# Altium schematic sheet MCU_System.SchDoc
size A4; SheetNumber: 2; SheetTotal: 4
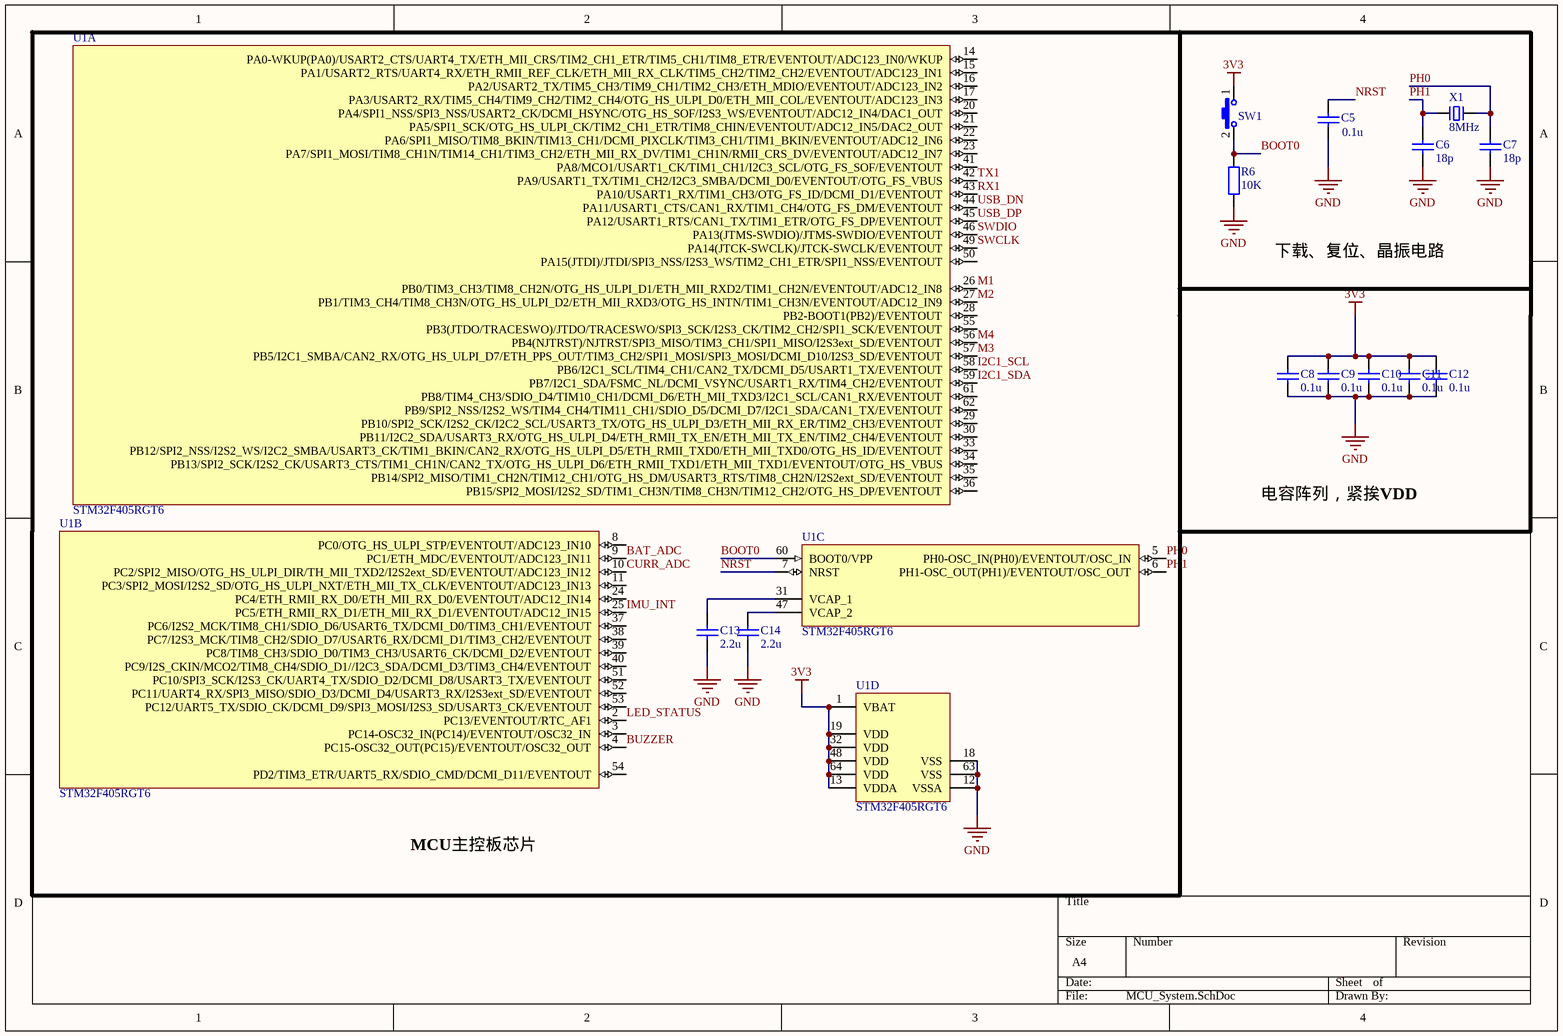
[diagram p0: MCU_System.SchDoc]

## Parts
C5  0.1u  [C0402_M]
C6  18p  [C0402_M]
C7  18p  [C0402_M]
C8  0.1u  [C0402_M]
C9  0.1u  [C0402_M]
C10  0.1u  [C0402_M]
C11  0.1u  [C0402_M]
C12  0.1u  [C0402_M]
C13  2.2u  [C0402_M]
C14  2.2u  [C0402_M]
R6  10K  [R0402_M]
SW1  3x6x5  [SW-SMD-2.8*2.4_4P]  (value not drawn)
U1  STM32F405RGT6  [TQFP64_M]  (parts A,B,C,D of 4)
X1  8MHz  [OSC-3225-4P]

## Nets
3V3: C8.2 C9.2 C10.2 C11.2 C12.2 SW1.1 U1.1(VBAT) U1.13(VDDA) U1.19(VDD) U1.32(VDD) U1.48(VDD) U1.64(VDD)
GND: C5.1 C6.1 C7.1 C8.1 C9.1 C10.1 C11.1 C12.1 C13.1 C14.1 R6.1 U1.12(VSSA) U1.18(VSS) U1.63(VSS)
BAT_ADC: U1.9(PC1/ETH_MDC/EVENTOUT/ADC123_IN11)
BOOT0: R6.2 SW1.2 U1.60(BOOT0/VPP)
BUZZER: U1.4(PC15-OSC32_OUT(PC15)/EVENTOUT/OSC32_OUT)
CURR_ADC: U1.10(PC2/SPI2_MISO/OTG_HS_ULPI_DIR/TH_MII_TXD2/I2S2ext_SD/EVENTOUT/ADC123_IN12)
I2C1_SCL: U1.58(PB6/I2C1_SCL/TIM4_CH1/CAN2_TX/DCMI_D5/USART1_TX/EVENTOUT)
I2C1_SDA: U1.59(PB7/I2C1_SDA/FSMC_NL/DCMI_VSYNC/USART1_RX/TIM4_CH2/EVENTOUT)
IMU_INT: U1.25(PC5/ETH_RMII_RX_D1/ETH_MII_RX_D1/EVENTOUT/ADC12_IN15)
LED_STATUS: U1.2(PC13/EVENTOUT/RTC_AF1)
M1: U1.26(PB0/TIM3_CH3/TIM8_CH2N/OTG_HS_ULPI_D1/ETH_MII_RXD2/TIM1_CH2N/EVENTOUT/ADC12_IN8)
M2: U1.27(PB1/TIM3_CH4/TIM8_CH3N/OTG_HS_ULPI_D2/ETH_MII_RXD3/OTG_HS_INTN/TIM1_CH3N/EVENTOUT/ADC12_IN9)
M3: U1.57(PB5/I2C1_SMBA/CAN2_RX/OTG_HS_ULPI_D7/ETH_PPS_OUT/TIM3_CH2/SPI1_MOSI/SPI3_MOSI/DCMI_D10/I2S3_SD/EVENTOUT)
M4: U1.56(PB4(NJTRST)/NJTRST/SPI3_MISO/TIM3_CH1/SPI1_MISO/I2S3ext_SD/EVENTOUT)
NRST: C5.2 U1.7(NRST)
PH0: C7.2 U1.5(PH0-OSC_IN(PH0)/EVENTOUT/OSC_IN) X1.3
PH1: C6.2 U1.6(PH1-OSC_OUT(PH1)/EVENTOUT/OSC_OUT) X1.1
RX1: U1.43(PA10/USART1_RX/TIM1_CH3/OTG_FS_ID/DCMI_D1/EVENTOUT)
SWCLK: U1.49(PA14(JTCK-SWCLK)/JTCK-SWCLK/EVENTOUT)
SWDIO: U1.46(PA13(JTMS-SWDIO)/JTMS-SWDIO/EVENTOUT)
TX1: U1.42(PA9/USART1_TX/TIM1_CH2/I2C3_SMBA/DCMI_D0/EVENTOUT/OTG_FS_VBUS)
USB_DN: U1.44(PA11/USART1_CTS/CAN1_RX/TIM1_CH4/OTG_FS_DM/EVENTOUT)
USB_DP: U1.45(PA12/USART1_RTS/CAN1_TX/TIM1_ETR/OTG_FS_DP/EVENTOUT)
NetC13_2: C13.2 U1.31(VCAP_1)
NetC14_2: C14.2 U1.47(VCAP_2)

Not connected (* = marked no-connect by the designer): U1 3(PC14-OSC32_IN(PC14)/EVENTOUT/OSC32_IN) 8(PC0/OTG_HS_ULPI_STP/EVENTOUT/ADC123_IN10) 11(PC3/SPI2_MOSI/I2S2_SD/OTG_HS_ULPI_NXT/ETH_MII_TX_CLK/EVENTOUT/ADC123_IN13) 14(PA0-WKUP(PA0)/USART2_CTS/UART4_TX/ETH_MII_CRS/TIM2_CH1_ETR/TIM5_CH1/TIM8_ETR/EVENTOUT/ADC123_IN0/WKUP) 15(PA1/USART2_RTS/UART4_RX/ETH_RMII_REF_CLK/ETH_MII_RX_CLK/TIM5_CH2/TIM2_CH2/EVENTOUT/ADC123_IN1) 16(PA2/USART2_TX/TIM5_CH3/TIM9_CH1/TIM2_CH3/ETH_MDIO/EVENTOUT/ADC123_IN2) 17(PA3/USART2_RX/TIM5_CH4/TIM9_CH2/TIM2_CH4/OTG_HS_ULPI_D0/ETH_MII_COL/EVENTOUT/ADC123_IN3) 20(PA4/SPI1_NSS/SPI3_NSS/USART2_CK/DCMI_HSYNC/OTG_HS_SOF/I2S3_WS/EVENTOUT/ADC12_IN4/DAC1_OUT) 21(PA5/SPI1_SCK/OTG_HS_ULPI_CK/TIM2_CH1_ETR/TIM8_CHIN/EVENTOUT/ADC12_IN5/DAC2_OUT) 22(PA6/SPI1_MISO/TIM8_BKIN/TIM13_CH1/DCMI_PIXCLK/TIM3_CH1/TIM1_BKIN/EVENTOUT/ADC12_IN6) 23(PA7/SPI1_MOSI/TIM8_CH1N/TIM14_CH1/TIM3_CH2/ETH_MII_RX_DV/TIM1_CH1N/RMII_CRS_DV/EVENTOUT/ADC12_IN7) 24(PC4/ETH_RMII_RX_D0/ETH_MII_RX_D0/EVENTOUT/ADC12_IN14) 28(PB2-BOOT1(PB2)/EVENTOUT) 29(PB10/SPI2_SCK/I2S2_CK/I2C2_SCL/USART3_TX/OTG_HS_ULPI_D3/ETH_MII_RX_ER/TIM2_CH3/EVENTOUT) 30(PB11/I2C2_SDA/USART3_RX/OTG_HS_ULPI_D4/ETH_RMII_TX_EN/ETH_MII_TX_EN/TIM2_CH4/EVENTOUT) 33(PB12/SPI2_NSS/I2S2_WS/I2C2_SMBA/USART3_CK/TIM1_BKIN/CAN2_RX/OTG_HS_ULPI_D5/ETH_RMII_TXD0/ETH_MII_TXD0/OTG_HS_ID/EVENTOUT) 34(PB13/SPI2_SCK/I2S2_CK/USART3_CTS/TIM1_CH1N/CAN2_TX/OTG_HS_ULPI_D6/ETH_RMII_TXD1/ETH_MII_TXD1/EVENTOUT/OTG_HS_VBUS) 35(PB14/SPI2_MISO/TIM1_CH2N/TIM12_CH1/OTG_HS_DM/USART3_RTS/TIM8_CH2N/I2S2ext_SD/EVENTOUT) 36(PB15/SPI2_MOSI/I2S2_SD/TIM1_CH3N/TIM8_CH3N/TIM12_CH2/OTG_HS_DP/EVENTOUT) 37(PC6/I2S2_MCK/TIM8_CH1/SDIO_D6/USART6_TX/DCMI_D0/TIM3_CH1/EVENTOUT) 38(PC7/I2S3_MCK/TIM8_CH2/SDIO_D7/USART6_RX/DCMI_D1/TIM3_CH2/EVENTOUT) 39(PC8/TIM8_CH3/SDIO_D0/TIM3_CH3/USART6_CK/DCMI_D2/EVENTOUT) 40(PC9/I2S_CKIN/MCO2/TIM8_CH4/SDIO_D1//I2C3_SDA/DCMI_D3/TIM3_CH4/EVENTOUT) 41(PA8/MCO1/USART1_CK/TIM1_CH1/I2C3_SCL/OTG_FS_SOF/EVENTOUT) 50(PA15(JTDI)/JTDI/SPI3_NSS/I2S3_WS/TIM2_CH1_ETR/SPI1_NSS/EVENTOUT) 51(PC10/SPI3_SCK/I2S3_CK/UART4_TX/SDIO_D2/DCMI_D8/USART3_TX/EVENTOUT) 52(PC11/UART4_RX/SPI3_MISO/SDIO_D3/DCMI_D4/USART3_RX/I2S3ext_SD/EVENTOUT) 53(PC12/UART5_TX/SDIO_CK/DCMI_D9/SPI3_MOSI/I2S3_SD/USART3_CK/EVENTOUT) 54(PD2/TIM3_ETR/UART5_RX/SDIO_CMD/DCMI_D11/EVENTOUT) 55(PB3(JTDO/TRACESWO)/JTDO/TRACESWO/SPI3_SCK/I2S3_CK/TIM2_CH2/SPI1_SCK/EVENTOUT) 61(PB8/TIM4_CH3/SDIO_D4/TIM10_CH1/DCMI_D6/ETH_MII_TXD3/I2C1_SCL/CAN1_RX/EVENTOUT) 62(PB9/SPI2_NSS/I2S2_WS/TIM4_CH4/TIM11_CH1/SDIO_D5/DCMI_D7/I2C1_SDA/CAN1_TX/EVENTOUT)

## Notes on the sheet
- 下载、复位、晶振电路
- 电容阵列，紧挨VDD
- MCU主控板芯片

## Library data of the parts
C5-C14 = C: 贴片电容/MLCC电容; BOM名称: 无极性贴片电容; 当前库版本V2022.12.25 @淘宝卖家:黄晶宝石: 最新版本发布https://shop463601444.taobao.com
R6 = R: 贴片电阻; 联系下单店铺卖家 免费帮你查找封装: 联系下单店铺卖家 免费技术支持
SW1 = SW-PB: 微动开关; BOM名称: 3x6轻触开关; 联系下单店铺卖家 免费技术支持: 联系下单店铺卖家 免费帮你查找封装
U1 = STM32F405RGT6: ARM Cortex-M4 32b MCU+FPU, 210DMIP, 1024 kB Flash, 192+4 kB RAM, 51 I/Os, 64-pin LQFP, -40 to +85癈, Tray; Internal RAM: 192kB; Operating Frequency (Processor Speed): 168MHz; A/D Converter: 16x12-bit; D/A Converter: 2x12-bit; 16-bit Timers (IC/OC/PWM): 12x16-bit(24/24/30); 32-bit Timer (IC/OC/PWM): 2x32-bit (8/8/8); Other Timer Functions: 2xWDG, RTC, 24-bit down counter; Serial Interface: 3xSPI/2xI2S/2xI2C/3xUSART(IrDa, ISO7816)/3xUART/1xUSB OTG FS/HS, 2xCAN/ SDIO; 联系卖家，免费查找封装: 唯一出售店铺网址https://shop463601444.taobao.com
X1 = XTAL-2P: 2脚无源晶振(谐振器）; 联系下单店铺卖家 免费帮你查找封装: 联系下单店铺卖家 免费技术支持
